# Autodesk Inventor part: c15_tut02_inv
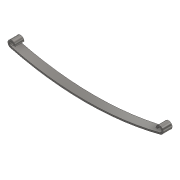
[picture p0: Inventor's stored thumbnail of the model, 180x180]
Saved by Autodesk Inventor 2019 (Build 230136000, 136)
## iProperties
Created: 2017-05
Part Number: c15_tut02_inv
Material: Steel, Mild
Document SubType Name: Modeling
Designer: CADCIM 00
Mass: 5.6491 g
Surface Area: 16.9114 cm^2
Volume: 0.71963 cm^3
Density: 7.85 g/cm^3
Appearance: Semi-Polished
Author: CADCIM 00
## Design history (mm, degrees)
sketch "Sketch1"
  geometry: L1 (0, 0)-(0, 18.068); L2 (48.5, 8.9)-(47.5, 8.9); L3 (-48.5, 8.9)-(-47.5, 8.9); A1 r 200 centre (0, 201) between (-50.378, 7.449) and (50.378, 7.449); A2 r 201 centre (0, 201) between (-50.63, 6.481) and (50.63, 6.481); A3 r 1.5 centre (50, 8.9) between (50.378, 7.449) and (48.5, 8.9); A4 r 2.5 centre (50, 8.9) between (50.63, 6.481) and (47.5, 8.9); A5 r 1.5 centre (-50, 8.9) between (-48.5, 8.9) and (-50.378, 7.449); A6 r 2.5 centre (-50, 8.9) between (-47.5, 8.9) and (-50.63, 6.481); 5 further points
  constraints: 13 point on circle, 6 centre point, 6 end point, 6 symmetric about line, 5 horizontal alignment, 3 coincident, 2 tangent, 1 horizontal, 1 midpoint, 1 vertical, 2 other
  dimensions: "d0" = 200 radius of A1; "d1" = 1 radial gap between concentric circles of A2 A1; "d2" = 2.5 radius of A4; "d3" = 50 distance from line of L1 A3.centre
extrude "Extrusion1" new body sketch "Sketch1" distance "d4" = 6; taper "d5" = 0 deg
body "Solid1"
